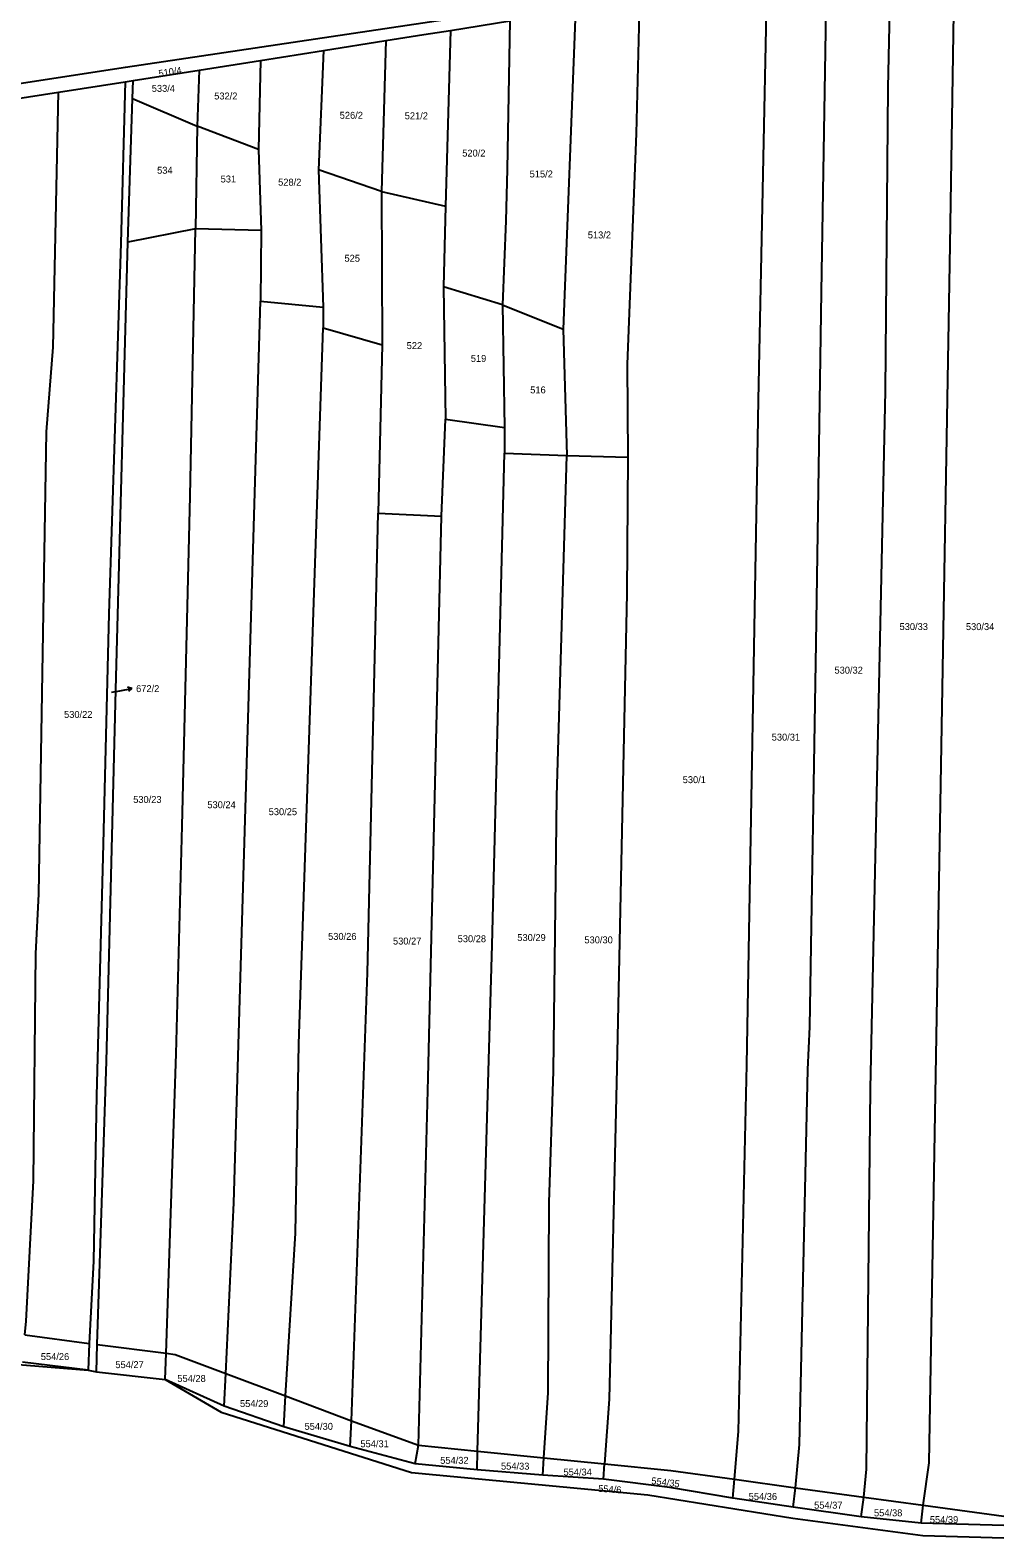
# Model space of a CAD drawing. Extents: x -7483133 to -743169, y -11317770 to -1127091.
# Drawn here: x -746642.5 to -746405.1, y -1133050.1 to -1132680.7 of the extents above; entities that cross this region are included whole.
import ezdxf

# ---------------------------------------------------------------- set-up
doc = ezdxf.new("R2010")
doc.units = 0
for name, color, linetype in [('Hranice parcel', 7, 'Continuous'), ('Parcelní čísla', 7, 'Continuous'), ('Pop  PČ popisy', 7, 'Continuous')]:
    doc.layers.add(name, color=color, linetype=linetype)

msp = doc.modelspace()

# ---------------------------------------------------------------- linework, layer by layer
at = {"layer": 'Hranice parcel'}
for p, q in [((-746539.48, -1132680.72), (-746524.93, -1132678.4)), ((-746508.88, -1132675.84), (-746511.87, -1132753.93)), ((-746539.48, -1132680.72), (-746540.7, -1132723.77)), ((-746586.05, -1132688.07), (-746570.65, -1132685.64)), ((-746570.65, -1132685.64), (-746571.83, -1132714.93)), ((-746570.65, -1132685.64), (-746555.32, -1132683.23)), ((-746555.32, -1132683.23), (-746556.39, -1132720.22)), ((-746601.09, -1132690.44), (-746586.05, -1132688.07)), ((-746586.05, -1132688.07), (-746586.58, -1132709.93)), ((-746635.57, -1132695.85), (-746619.25, -1132693.34)), ((-746619.25, -1132693.34), (-746617.26, -1132692.98)), ((-746617.4, -1132697.45), (-746617.26, -1132692.98)), ((-746617.26, -1132692.98), (-746601.09, -1132690.44)), ((-746601.09, -1132690.44), (-746601.56, -1132704.22)), ((-746650.38, -1132698.13), (-746635.57, -1132695.85)), ((-746618.54, -1132732.6), (-746617.4, -1132697.45)), ((-746617.4, -1132697.45), (-746601.56, -1132704.22)), ((-746601.56, -1132704.22), (-746601.99, -1132729.34)), ((-746586.58, -1132709.93), (-746601.56, -1132704.22)), ((-746586.58, -1132709.93), (-746585.86, -1132729.78)), ((-746556.39, -1132720.22), (-746571.83, -1132714.93)), ((-746571.83, -1132714.93), (-746570.67, -1132748.51)), ((-746556.39, -1132720.22), (-746540.7, -1132723.77)), ((-746556.39, -1132720.22), (-746556.24, -1132757.76)), ((-746540.7, -1132723.77), (-746541.24, -1132743.54)), ((-746601.99, -1132729.34), (-746618.54, -1132732.6)), ((-746585.86, -1132729.78), (-746601.99, -1132729.34)), ((-746585.86, -1132729.78), (-746586.08, -1132747.08)), ((-746526.72, -1132747.96), (-746541.24, -1132743.54)), ((-746541.24, -1132743.54), (-746540.69, -1132776.03)), ((-746586.08, -1132747.08), (-746570.67, -1132748.51)), ((-746570.67, -1132748.51), (-746570.67, -1132753.65)), ((-746526.72, -1132747.96), (-746511.87, -1132753.93)), ((-746526.72, -1132747.96), (-746526.28, -1132778.03)), ((-746570.67, -1132753.65), (-746556.24, -1132757.76)), ((-746511.87, -1132753.93), (-746511.02, -1132784.9)), ((-746556.24, -1132757.76), (-746557.24, -1132799.02)), ((-746541.69, -1132799.73), (-746540.69, -1132776.03)), ((-746540.69, -1132776.03), (-746526.28, -1132778.03)), ((-746526.28, -1132778.03), (-746526.28, -1132784.31)), ((-746526.28, -1132784.31), (-746511.02, -1132784.9)), ((-746511.02, -1132784.9), (-746496.03, -1132785.34)), ((-746557.24, -1132799.02), (-746541.69, -1132799.73)), ((-746643.78, -1133000.37), (-746628.03, -1133002.49)), ((-746628.03, -1133002.49), (-746628.31, -1133009.07)), ((-746626.24, -1133009.42), (-746626.1, -1133002.71)), ((-746626.1, -1133002.71), (-746609.17, -1133004.9)), ((-746628.31, -1133009.07), (-746644.4, -1133007.07)), ((-746609.38, -1133011.3), (-746609.17, -1133004.9)), ((-746628.31, -1133009.07), (-746626.24, -1133009.42)), ((-746626.24, -1133009.42), (-746609.38, -1133011.3)), ((-746594.92, -1133017.88), (-746609.38, -1133011.3)), ((-746594.92, -1133017.88), (-746594.55, -1133009.86)), ((-746594.55, -1133009.86), (-746579.91, -1133015.36)), ((-746580.36, -1133022.88), (-746594.92, -1133017.88)), ((-746580.36, -1133022.88), (-746579.91, -1133015.36)), ((-746579.91, -1133015.36), (-746563.76, -1133021.43)), ((-746564.09, -1133027.73), (-746563.76, -1133021.43)), ((-746563.76, -1133021.43), (-746547.35, -1133027.42)), ((-746564.09, -1133027.73), (-746580.36, -1133022.88)), ((-746548.12, -1133032), (-746564.09, -1133027.73)), ((-746548.12, -1133032), (-746547.35, -1133027.42)), ((-746547.35, -1133027.42), (-746532.86, -1133028.88)), ((-746532.99, -1133033.43), (-746532.86, -1133028.88)), ((-746532.86, -1133028.88), (-746516.59, -1133030.52)), ((-746532.99, -1133033.43), (-746548.12, -1133032)), ((-746516.86, -1133034.73), (-746532.99, -1133033.43)), ((-746516.86, -1133034.73), (-746516.59, -1133030.52)), ((-746516.59, -1133030.52), (-746501.75, -1133032.02)), ((-746502.02, -1133035.72), (-746501.75, -1133032.02)), ((-746502.02, -1133035.72), (-746516.86, -1133034.73)), ((-746470.34, -1133040.43), (-746469.94, -1133035.78)), ((-746469.94, -1133035.78), (-746454.93, -1133037.84)), ((-746455.5, -1133042.58), (-746470.34, -1133040.43)), ((-746455.5, -1133042.58), (-746454.93, -1133037.84)), ((-746454.93, -1133037.84), (-746438.18, -1133040.13)), ((-746438.82, -1133045), (-746438.18, -1133040.13)), ((-746438.18, -1133040.13), (-746423.66, -1133042.13)), ((-746438.82, -1133045), (-746455.5, -1133042.58)), ((-746424.12, -1133046.56), (-746423.66, -1133042.13)), ((-746423.66, -1133042.13), (-746403.94, -1133044.84)), ((-746424.12, -1133046.56), (-746438.82, -1133045)), ((-746403.86, -1133047.13), (-746424.12, -1133046.56))]:
    msp.add_line(p, q, dxfattribs=at)
for points in [[(-746898.28, -1132733.66), (-746836.86, -1132723.53), (-746713.33, -1132704.19), (-746619.13, -1132689.77), (-746522.21, -1132675.28), (-746408.39, -1132656.58), (-746328.84, -1132643.04)], [(-746438.18, -1133040.13), (-746437.53, -1133033.27), (-746436.57, -1132940.05), (-746432.87, -1132769.03), (-746432.24, -1132694.84), (-746431.66, -1132668.15), (-746431.15, -1132663.43)], [(-746423.66, -1133042.13), (-746422.21, -1133031.75), (-746419.43, -1132870.16), (-746417.02, -1132733.26), (-746415.89, -1132660.88)], [(-746454.93, -1133037.84), (-746453.95, -1133027.27), (-746451.93, -1132935.37), (-746451.41, -1132924.92), (-746449.85, -1132830.84), (-746448.56, -1132744.9), (-746447.3, -1132666.01)], [(-746469.94, -1133035.78), (-746468.91, -1133024.02), (-746466.91, -1132934.23), (-746464.06, -1132771.35), (-746461.92, -1132668.34)], [(-746493.19, -1132673.33), (-746494.03, -1132705.97), (-746496.17, -1132762.5), (-746496.03, -1132785.34)], [(-746524.93, -1132678.4), (-746525.58, -1132714.77), (-746525.93, -1132727.41), (-746526.72, -1132747.96)], [(-746555.32, -1132683.23), (-746546.04, -1132681.77), (-746539.48, -1132680.72)], [(-746619.25, -1132693.34), (-746620.26, -1132732.88), (-746623.23, -1132823.67), (-746624.66, -1132883.35), (-746626.23, -1132941.74), (-746626.96, -1132982.3), (-746628.03, -1133002.49)], [(-746643.78, -1133000.37), (-746643.47, -1132997), (-746641.69, -1132962.6), (-746641.11, -1132906.92), (-746640.39, -1132892.35), (-746638.47, -1132779.07), (-746636.9, -1132758.37), (-746635.57, -1132695.85)], [(-746609.17, -1133004.9), (-746606.76, -1132931.52), (-746605.27, -1132875.67), (-746603.27, -1132794.87), (-746601.99, -1132729.34)], [(-746626.1, -1133002.71), (-746623.82, -1132933.33), (-746621.46, -1132839.1), (-746618.54, -1132732.6)], [(-746594.55, -1133009.86), (-746592.63, -1132968.06), (-746591.35, -1132926.52), (-746590.07, -1132882.4), (-746586.08, -1132747.08)], [(-746579.91, -1133015.36), (-746577.51, -1132975.49), (-746576.65, -1132929.09), (-746570.67, -1132753.65)], [(-746532.86, -1133028.88), (-746529.27, -1132904.8), (-746526.28, -1132784.31)], [(-746516.59, -1133030.52), (-746515.58, -1133014.6), (-746515.29, -1132967.92), (-746514.29, -1132935.8), (-746513.44, -1132868.4), (-746511.02, -1132784.9)], [(-746496.03, -1132785.34), (-746496.32, -1132818.74), (-746498.74, -1132935.09), (-746500.59, -1133016.17), (-746501.75, -1133032.02)], [(-746563.76, -1133021.43), (-746559.81, -1132911.66), (-746557.24, -1132799.02)], [(-746547.35, -1133027.42), (-746544.98, -1132937.36), (-746541.69, -1132799.73)], [(-746929.35, -1132954.76), (-746891.82, -1132961.76), (-746852.29, -1132968.9), (-746817.33, -1132976.32), (-746744.69, -1132994.17), (-746722.86, -1132997.73), (-746660.65, -1133006.44), (-746628.31, -1133009.07)], [(-746609.17, -1133004.9), (-746606.99, -1133005.18), (-746594.55, -1133009.86)], [(-746609.38, -1133011.3), (-746595.72, -1133019.29), (-746549.06, -1133034.13), (-746491.13, -1133039.56), (-746455.59, -1133045.27), (-746423.77, -1133049.55), (-746403.94, -1133050.12)], [(-746501.75, -1133032.02), (-746485.49, -1133033.63), (-746469.94, -1133035.78)], [(-746470.34, -1133040.43), (-746485.71, -1133037.77), (-746502.02, -1133035.72)]]:
    msp.add_lwpolyline(points, dxfattribs=at)
at = {"layer": 'Pop  PČ popisy'}
for p, q in [((-746622.53, -1132842.89), (-746620.5, -1132842.54)), ((-746620.5, -1132842.54), (-746617.55, -1132842.02)), ((-746617.55, -1132842.02), (-746618.62, -1132841.7)), ((-746617.55, -1132842.02), (-746618.44, -1132842.69))]:
    msp.add_line(p, q, dxfattribs=at)

# ---------------------------------------------------------------- texts
at = {"layer": 'Parcelní čísla'}
for s, rotation, p in [('510/4', 9, (-746610.9, -1132692.17)), ('554/6', 356, (-746503.35, -1133038.84)), ('554/35', 353, (-746490.36, -1133036.93))]:
    msp.add_text(s, height=1.7, rotation=rotation, dxfattribs=at).set_placement(p)
for s, p in [('533/4', (-746612.7, -1132695.78)), ('532/2', (-746597.4, -1132697.65)), ('526/2', (-746566.64, -1132702.38)), ('521/2', (-746550.71, -1132702.5)), ('520/2', (-746536.62, -1132711.64)), ('534', (-746611.39, -1132715.85)), ('515/2', (-746520.1, -1132716.76)), ('531', (-746595.82, -1132717.99)), ('528/2', (-746581.73, -1132718.77)), ('513/2', (-746505.85, -1132731.7)), ('525', (-746565.47, -1132737.41)), ('522', (-746550.23, -1132758.82)), ('519', (-746534.52, -1132761.96)), ('516', (-746519.96, -1132769.67)), ('530/33', (-746429.45, -1132827.67)), ('530/34', (-746413.19, -1132827.68)), ('530/32', (-746445.4, -1132838.35)), ('672/2', (-746616.54, -1132842.88)), ('530/22', (-746634.19, -1132849.19)), ('530/31', (-746460.78, -1132854.76)), ('530/1', (-746482.59, -1132865.18)), ('530/23', (-746617.25, -1132870.03)), ('530/24', (-746599.07, -1132871.32)), ('530/25', (-746584.05, -1132873.03)), ('530/26', (-746569.49, -1132903.58)), ('530/27', (-746553.59, -1132904.73)), ('530/28', (-746537.74, -1132904.16)), ('530/29', (-746523.12, -1132903.87)), ('530/30', (-746506.68, -1132904.44)), ('554/26', (-746639.89, -1133006.55)), ('554/27', (-746621.62, -1133008.53)), ('554/28', (-746606.43, -1133011.92)), ('554/29', (-746591.08, -1133018.07)), ('554/30', (-746575.26, -1133023.65)), ('554/31', (-746561.57, -1133027.91)), ('554/32', (-746542.02, -1133031.98)), ('554/33', (-746527.12, -1133033.41)), ('554/34', (-746511.8, -1133034.84)), ('554/36', (-746466.42, -1133040.83)), ('554/37', (-746450.39, -1133042.97)), ('554/38', (-746435.72, -1133044.85)), ('554/39', (-746422.03, -1133046.5))]:
    msp.add_text(s, height=1.7, dxfattribs=at).set_placement(p)

doc.saveas('drawing.dxf')
